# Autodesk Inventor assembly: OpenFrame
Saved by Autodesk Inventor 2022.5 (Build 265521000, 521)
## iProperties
Created: 2024-05
Part Number: OpenFrame
Document SubType Name: Assembly
Designer: AdminForWorker
Title: OpenFrame v1
Author: AdminForWorker
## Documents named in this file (7)
- c:\worker\convert-fusion-r02-cosv3\tmp\job-1\35\temp\files\768f1e71-da1e-4741-823a-125cdcc5787c\87f0871c-e1bb-4ca6-a49c-fe5756ad3517.iam
- c:\worker\convert-fusion-r02-cosv3\tmp\job-1\35\temp\files\768f1e71-da1e-4741-823a-125cdcc5787c\OF-LL-BP v1.ipt
- c:\worker\convert-fusion-r02-cosv3\tmp\job-1\35\temp\files\768f1e71-da1e-4741-823a-125cdcc5787c\OpenFrame v1.iam
- c:\worker\convert-fusion-r02-cosv3\tmp\job-1\35\temp\files\768f1e71-da1e-4741-823a-125cdcc5787c\OF-LL-FL-MOT v1.ipt
- c:\worker\convert-fusion-r02-cosv3\tmp\job-1\35\temp\files\768f1e71-da1e-4741-823a-125cdcc5787c\OF-AD-SBSM2-CM v1.ipt
- c:\worker\convert-fusion-r02-cosv3\tmp\job-1\35\temp\files\768f1e71-da1e-4741-823a-125cdcc5787c\OF-IN-MCH v1.ipt
- c:\worker\convert-fusion-r02-cosv3\tmp\job-1\35\temp\files\768f1e71-da1e-4741-823a-125cdcc5787c\OF-LL-SP v1.ipt
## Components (6 placed, 6 different names)
1. OF-LL-BP v1:1
2. OpenFrame v1:1 [sub-assembly]
3. OF-LL-FL-MOT v1:1
4. OF-AD-SBSM2-CM v1:1
5. OF-IN-MCH v1:1
6. OF-LL-SP v1:1
